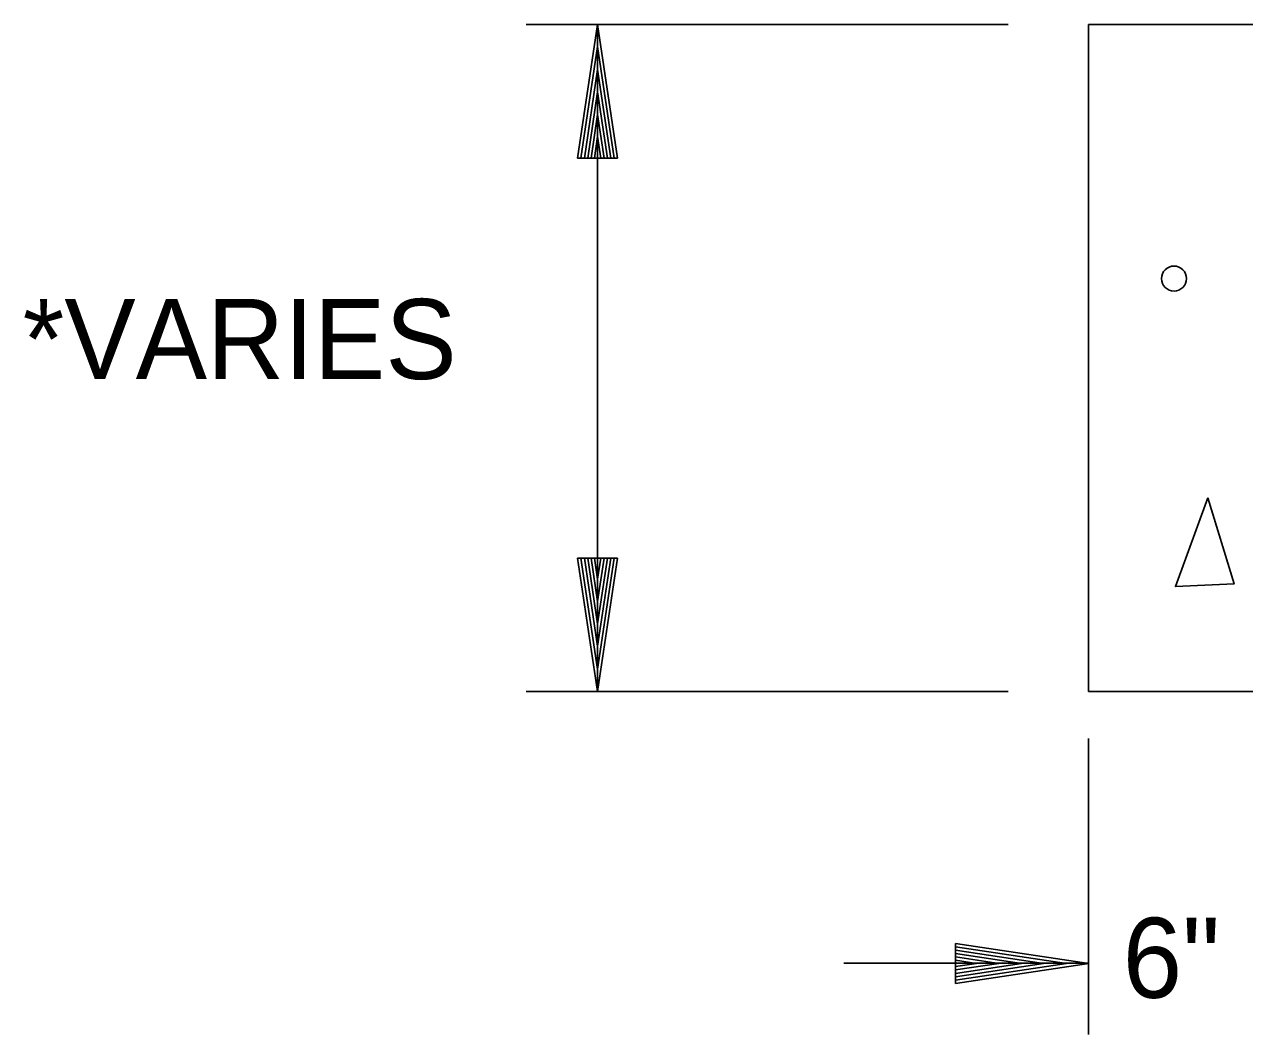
# Model space of a CAD drawing. Extents: x -2842 to 2681, y -2139 to 474.
# Drawn here: x -726.7 to -635.2, y -1563.3 to -1487.5 of the extents above; entities that cross this region are included whole.
import ezdxf

# ---------------------------------------------------------------- set-up
doc = ezdxf.new("R2010")
doc.units = 0
doc.layers.add('Default', color=7, linetype='Continuous')

msp = doc.modelspace()

# ---------------------------------------------------------------- linework, layer by layer
at = {"layer": 'Default'}
for p, q in [((-652.901, -1487.539), (-689.037, -1487.539)), ((-685.202, -1497.552), (-683.702, -1487.553)), ((-682.202, -1497.552), (-683.702, -1487.553)), ((-683.698, -1487.539), (-683.698, -1537.536)), ((-646.868, -1487.539), (265.574, -1487.539)), ((-646.868, -1537.536), (-646.868, -1487.539)), ((-684.952, -1497.552), (-683.702, -1489.203)), ((-682.452, -1497.552), (-683.702, -1489.203)), ((-684.677, -1497.552), (-683.702, -1490.928)), ((-682.702, -1497.552), (-683.702, -1490.928)), ((-684.427, -1497.552), (-683.702, -1492.603)), ((-682.952, -1497.552), (-683.702, -1492.603)), ((-684.177, -1497.552), (-683.702, -1494.303)), ((-683.202, -1497.552), (-683.702, -1494.303)), ((-683.927, -1497.552), (-683.702, -1495.952)), ((-683.452, -1497.552), (-683.702, -1495.952)), ((-685.202, -1497.552), (-682.202, -1497.552)), ((-685.202, -1527.55), (-683.702, -1537.55)), ((-682.202, -1527.55), (-685.202, -1527.55)), ((-684.952, -1527.55), (-683.702, -1535.875)), ((-684.677, -1527.55), (-683.702, -1534.15)), ((-684.427, -1527.55), (-683.702, -1532.475)), ((-684.177, -1527.55), (-683.702, -1530.8)), ((-683.927, -1527.55), (-683.702, -1529.125)), ((-682.202, -1527.55), (-683.702, -1537.55)), ((-683.202, -1527.55), (-683.702, -1530.8)), ((-682.702, -1527.55), (-683.702, -1534.15)), ((-682.452, -1527.55), (-683.702, -1535.875)), ((-682.952, -1527.55), (-683.702, -1532.475)), ((-683.452, -1527.55), (-683.702, -1529.125)), ((-652.901, -1537.536), (-689.037, -1537.536)), ((-634.369, -1537.536), (-646.868, -1537.536)), ((-646.868, -1541.07), (-646.868, -1563.256)), ((-656.853, -1556.424), (-646.854, -1557.923)), ((-656.853, -1556.424), (-656.853, -1559.423)), ((-656.853, -1556.674), (-648.529, -1557.923)), ((-656.853, -1556.924), (-650.254, -1557.923)), ((-656.853, -1557.174), (-651.904, -1557.923)), ((-656.853, -1557.424), (-653.603, -1557.923)), ((-646.868, -1557.915), (-665.22, -1557.915)), ((-656.853, -1557.674), (-655.278, -1557.923)), ((-656.853, -1559.423), (-646.854, -1557.923)), ((-656.853, -1558.398), (-653.603, -1557.923)), ((-656.853, -1558.923), (-650.254, -1557.923)), ((-656.853, -1559.173), (-648.529, -1557.923)), ((-656.853, -1558.673), (-651.904, -1557.923)), ((-656.853, -1558.148), (-655.278, -1557.923))]:
    msp.add_line(p, q, dxfattribs=at)
msp.add_lwpolyline([(-637.929, -1523.026), (-640.354, -1529.675), (-635.955, -1529.475), (-637.929, -1523.026)], dxfattribs=at)
msp.add_circle((-640.455, -1506.589), 0.937, dxfattribs=at)

# ---------------------------------------------------------------- texts
for s, p in [('*VARIES', (-726.8, -1514.12)), ('6"', (-644.304, -1560.499))]:
    msp.add_text(s, height=6, dxfattribs=at).set_placement(p)

doc.saveas('drawing.dxf')
